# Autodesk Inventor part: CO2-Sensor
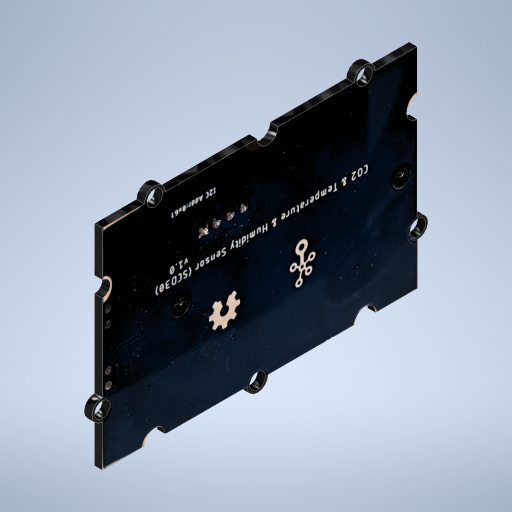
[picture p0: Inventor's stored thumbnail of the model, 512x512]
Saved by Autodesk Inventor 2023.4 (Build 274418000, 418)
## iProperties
Created: 2022-12
Part Number: CO2-Sensor
Material: Générique
Document SubType Name: Modeling
Designer: ecuenot
Density: 1 g/cm^3
Appearance: Noir
Author: ecuenot
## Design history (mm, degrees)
sketch "Esquisse1"
  geometry: L1 (8.143, -20)-(0.048, -20); L2 (8.048, 40.094)-(0.048, 40.094); L3 (40.048, -19.906)-(32.048, -19.906); L4 (28.048, -19.906)-(11.948, -19.906); L5 (40.048, -11.906)-(40.048, -19.906); L6 (40.048, 6.594)-(40.048, -7.906); L7 (40.048, 40.094)-(40.048, 32.094); L8 (40.048, 28.094)-(40.048, 10.594); L9 (40.048, 40.094)-(31.495, 40.094); L10 (28.495, 40.094)-(12.048, 40.094); L11 (0.048, 40.094)-(0.048, 32.094); L12 (0.048, 28.094)-(0.048, 12.5); L13 (0.048, 8.5)-(0.048, -8); L14 (0.048, -12)-(0.048, -20); C1 r 1.5 at (10.048, 40.094); C2 r 1.5 at (10.048, -20.07); C3 r 1.5 at (40.048, -9.906); C4 r 1.5 at (40.048, 30.094); C5 r 1.5 at (0.048, 10.5); A1 r 1.907 centre (10.048, -20.07) between (8.143, -20) and (11.948, -19.906); A2 r 2 centre (0.048, 10.5) between (0.048, 12.5) and (0.048, 8.5); A3 r 2 centre (40.048, 30.094) between (40.048, 28.094) and (40.048, 32.094); A4 r 2 centre (40.048, 8.594) between (40.048, 10.594) and (40.048, 6.594); A5 r 2 centre (40.048, -9.906) between (40.048, -11.906) and (40.048, -7.906); A6 r 1.5 centre (29.995, 40.094) between (28.495, 40.094) and (31.495, 40.094); A7 r 2 centre (30.048, -19.906) between (32.048, -19.906) and (28.048, -19.906); A8 r 2 centre (0.048, 30.094) between (0.048, 28.094) and (0.048, 32.094); A9 r 2 centre (0.048, -10) between (0.048, -12) and (0.048, -8); A10 r 2 centre (10.048, 40.094) between (12.048, 40.094) and (8.048, 40.094); 1 further point
  constraints: 28 end point, 20 point on circle, 18 perpendicular, 15 centre point, 5 coincident, 4 vertical, 3 horizontal
  dimensions: "d0" = 40 distance of L3.start L1.end; "d1" = 60 distance of L7.start L3.start; "d48" = 3 diameter of C1; "d246" = 4 diameter of A2; "d247" = 4 diameter of A3; "d248" = 4 diameter of A5; "d249" = 4 diameter of A10; "d250" = 4 diameter of A9; "d251" = 4 diameter of A8; "d252" = 4 diameter of A4; "d255" = 10 distance from line of L2 A8.centre; "d256" = 10 distance from line of L1 A9.centre; "d261" = 4 diameter of A7; "d262" = 3 diameter of C2; "d263" = 3 diameter of C3; "d264" = 3 diameter of C4; "d265" = 1.5 radius of A6; "d266" = 3 diameter of C5
extrude "Extrusion28" new body sketch "Esquisse1" distance "d267" = 1.5; taper "d268" = 0 deg
sketch "Esquisse37"
  geometry: L1 (19.906, 32.048)-(19.906, 40.048) reference; L2 (19.906, 40.048)-(19.707, -0.233); L3 (19.707, -0.233)-(-40.089, 0.062); L4 (-40.089, 0.062)-(-39.89, 40.343); L5 (-39.89, 40.343)-(19.906, 40.048); 1 further point; 1 other entity
  constraints: 2 other
feature "Décalcomanie5" sketch "Esquisse37"
sketch "Esquisse38"
  geometry: L1 (40.094, 40.048)-(40.094, 31.495) reference; L2 (40.094, 40.048)-(39.765, -0.413); L3 (39.765, -0.413)-(-19.993, 0.073); L4 (-19.993, 0.073)-(-19.664, 40.533); L5 (-19.664, 40.533)-(40.094, 40.048); 1 further point; 1 other entity
  constraints: 2 other
feature "Décalcomanie6" sketch "Esquisse38"
node "Solide2"
node "Image11"
node "Image12"
other parameters: "d213" = 5, "d214" = 5
